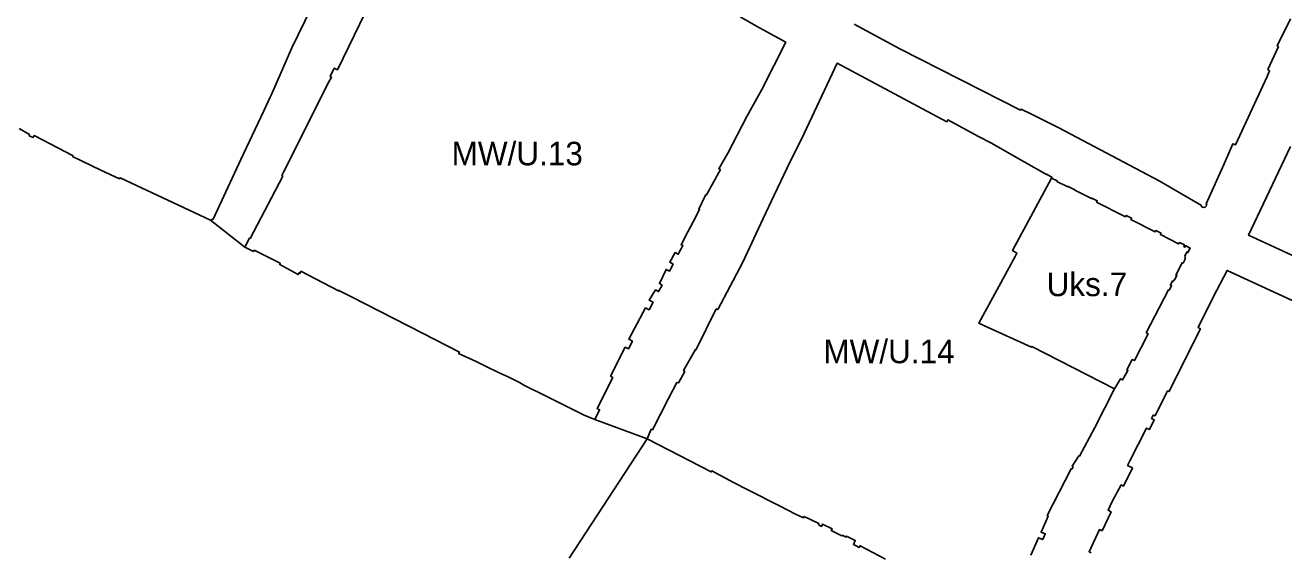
# Model space of a CAD drawing. Extents: x 7423367 to 7424726, y 5546744 to 5548391.
# Drawn here: x 7423927 to 7424194.2, y 5547840.8 to 5547952.8 of the extents above; entities that cross this region are included whole.
import ezdxf

# ---------------------------------------------------------------- set-up
doc = ezdxf.new("R2010")
doc.units = 0
doc.layers.add('linie_rozgraniczajace', color=7, linetype='Continuous')
doc.layers.add('oznaczenia_przeznaczen', color=7, linetype='Continuous')

msp = doc.modelspace()

# ---------------------------------------------------------------- linework, layer by layer
at = {"layer": 'linie_rozgraniczajace'}
for points in [[(7424002.7, 5547962.78), (7423993.29, 5547943.33), (7423992.63, 5547943.68), (7423991.75, 5547941.94), (7423992.02, 5547941.8), (7423991.4, 5547940.63), (7423990.46, 5547938.9), (7423983.05, 5547923.94), (7423981.87, 5547921.59), (7423981.51, 5547920.89), (7423981.69, 5547920.8), (7423974.77, 5547907.55), (7423974.64, 5547907.62), (7423973.68, 5547905.68), (7423966.33, 5547911.4), (7423966.92, 5547911.63), (7423972.83, 5547924.32), (7423977.68, 5547934.66), (7423979.01, 5547937.55), (7423979.3, 5547938.13), (7423983.64, 5547948.01), (7423987.74, 5547956.39)], [(7424078.76, 5547954.61), (7424082.89, 5547952.26), (7424088.46, 5547949.18), (7424083.38, 5547939.15), (7424080.22, 5547933.41), (7424076.17, 5547925.64), (7424074.24, 5547922.34), (7424074.58, 5547922.16), (7424071.66, 5547916.78), (7424071.52, 5547916.86), (7424069.97, 5547913.79), (7424070.15, 5547913.7), (7424068.8, 5547911.1), (7424067.69, 5547908.98), (7424066.23, 5547906.21), (7424066.61, 5547906.02), (7424065.64, 5547904.2), (7424064.97, 5547904.56), (7424063.83, 5547902.49), (7424064.55, 5547902.12), (7424063.76, 5547900.6), (7424063.06, 5547900.97), (7424061.64, 5547897.97), (7424062.24, 5547897.61), (7424061.46, 5547896.27), (7424060.83, 5547896.64), (7424059.49, 5547894.42), (7424060.28, 5547894.02), (7424059.46, 5547892.41), (7424058.69, 5547892.82), (7424055.18, 5547886.15), (7424055.91, 5547885.78), (7424055.09, 5547884.15), (7424054.4, 5547884.45), (7424051.22, 5547878.32), (7424051.78, 5547878.01), (7424048.41, 5547871.45), (7424048.94, 5547871.19), (7424047.91, 5547869.11), (7424045.7, 5547870.04), (7424037.48, 5547874.13), (7424033, 5547876.33), (7424031.91, 5547876.94), (7424029.7, 5547878.12), (7424027.6, 5547879.02), (7424027.21, 5547879.24), (7424025.15, 5547880.24), (7424024.28, 5547880.66), (7424022.72, 5547881.4), (7424021.94, 5547881.79), (7424019.78, 5547882.77), (7424019.03, 5547883.15), (7424019.18, 5547883.44), (7424011.38, 5547887.44), (7423996.29, 5547895.17), (7423993.59, 5547896.53), (7423993.52, 5547896.41), (7423985.54, 5547900.58), (7423985.34, 5547900.14), (7423985.11, 5547900.24), (7423984.95, 5547899.89), (7423981.05, 5547902), (7423981.18, 5547902.29), (7423975.63, 5547905.04), (7423975.48, 5547904.75), (7423973.68, 5547905.68), (7423974.64, 5547907.62), (7423974.77, 5547907.55), (7423981.69, 5547920.8), (7423981.51, 5547920.89), (7423981.87, 5547921.59), (7423983.05, 5547923.94), (7423990.46, 5547938.9), (7423991.4, 5547940.63), (7423992.02, 5547941.8), (7423991.75, 5547941.94), (7423992.63, 5547943.68), (7423993.29, 5547943.33), (7424002.7, 5547962.78)], [(7423987.74, 5547956.39), (7423983.64, 5547948.01), (7423979.3, 5547938.13), (7423979.01, 5547937.55), (7423977.68, 5547934.66), (7423972.83, 5547924.32), (7423966.92, 5547911.63), (7423966.33, 5547911.4), (7423957.28, 5547915.66), (7423947.17, 5547920.43), (7423947.03, 5547920.17), (7423943.08, 5547922.06), (7423937.1, 5547924.94), (7423937.19, 5547925.09), (7423928.92, 5547929.38), (7423928.72, 5547928.94), (7423927.85, 5547929.33), (7423927.97, 5547929.6), (7423925.73, 5547930.91)], [(7424140.46, 5547840.34), (7424142.09, 5547844.01), (7424143.01, 5547843.64), (7424143.53, 5547844.83), (7424142.63, 5547845.23), (7424144.13, 5547848.64), (7424143.94, 5547848.73), (7424148.99, 5547858.67), (7424149.16, 5547858.59), (7424149.44, 5547859.05), (7424149.26, 5547859.2), (7424150.62, 5547861.41), (7424150.79, 5547861.32), (7424153.96, 5547867.28), (7424158.25, 5547875.6), (7424159.47, 5547877.76), (7424159.95, 5547877.54), (7424161.07, 5547879.53), (7424160.85, 5547879.66), (7424161.97, 5547881.85), (7424162.46, 5547881.63), (7424165.35, 5547887.33), (7424164.95, 5547887.54), (7424169.67, 5547896.63), (7424169.83, 5547896.59), (7424170.32, 5547897.5), (7424170.08, 5547897.63), (7424170.53, 5547898.54), (7424170.68, 5547898.46), (7424170.89, 5547898.77), (7424170.98, 5547898.74), (7424171.46, 5547899.65), (7424171.25, 5547899.75), (7424172.58, 5547902.39), (7424172.78, 5547902.31), (7424173.27, 5547903.27), (7424173.13, 5547903.35), (7424173.28, 5547903.67), (7424173.12, 5547903.77), (7424173.56, 5547904.68), (7424173.8, 5547904.54), (7424174.28, 5547905.49), (7424173.33, 5547905.99), (7424173.18, 5547905.71), (7424172.91, 5547905.87), (7424173.05, 5547906.16), (7424172.03, 5547906.68), (7424171.83, 5547906.38), (7424167.96, 5547908.35), (7424168.11, 5547908.64), (7424167, 5547909.21), (7424166.84, 5547908.93), (7424161.68, 5547911.57), (7424161.84, 5547911.86), (7424160.71, 5547912.42), (7424160.55, 5547912.12), (7424154.4, 5547915.26), (7424154.56, 5547915.55), (7424153.43, 5547916.11), (7424153.37, 5547916), (7424149.77, 5547917.79), (7424149.8, 5547917.83), (7424148.38, 5547918.59), (7424148.31, 5547918.49), (7424146, 5547919.65), (7424146.06, 5547919.76), (7424144.84, 5547920.37), (7424144.94, 5547920.57), (7424143.81, 5547921.19), (7424143.77, 5547921.11), (7424139.04, 5547923.78), (7424131.97, 5547927.83), (7424129.35, 5547929.17), (7424122.83, 5547932.69), (7424122.64, 5547932.33), (7424099.38, 5547944.77), (7424091.79, 5547928.64), (7424089.43, 5547924.01), (7424086.02, 5547916.7), (7424083.68, 5547911.78), (7424079.28, 5547902.37), (7424074.01, 5547892.44), (7424073.69, 5547892.6), (7424069.44, 5547883.97), (7424069.32, 5547883.99), (7424066.78, 5547879.5), (7424067.02, 5547879.3), (7424065.7, 5547876.9), (7424065.35, 5547876.99), (7424063.59, 5547873.55), (7424060.14, 5547866.91), (7424059.9, 5547867.04), (7424059.01, 5547865.01), (7424047.91, 5547869.11), (7424048.94, 5547871.19), (7424048.41, 5547871.45), (7424051.78, 5547878.01), (7424051.22, 5547878.32), (7424054.4, 5547884.45), (7424055.09, 5547884.15), (7424055.91, 5547885.78), (7424055.18, 5547886.15), (7424058.69, 5547892.82), (7424059.46, 5547892.41), (7424060.28, 5547894.02), (7424059.49, 5547894.42), (7424060.83, 5547896.64), (7424061.46, 5547896.27), (7424062.24, 5547897.61), (7424061.64, 5547897.97), (7424063.06, 5547900.97), (7424063.76, 5547900.6), (7424064.55, 5547902.12), (7424063.83, 5547902.49), (7424064.97, 5547904.56), (7424065.64, 5547904.2), (7424066.61, 5547906.02), (7424066.23, 5547906.21), (7424067.69, 5547908.98), (7424068.8, 5547911.1), (7424070.15, 5547913.7), (7424069.97, 5547913.79), (7424071.52, 5547916.86), (7424071.66, 5547916.78), (7424074.58, 5547922.16), (7424074.24, 5547922.34), (7424076.17, 5547925.64), (7424080.22, 5547933.41), (7424083.38, 5547939.15), (7424088.46, 5547949.18), (7424082.89, 5547952.26), (7424078.76, 5547954.61)], [(7424195.6, 5547954.18), (7424192.76, 5547948.4), (7424193.02, 5547948.27), (7424190.77, 5547943.38), (7424191.12, 5547943.15), (7424190.93, 5547942.65), (7424190.6, 5547941.92), (7424183.9, 5547927.38), (7424183.31, 5547927.65), (7424181.5, 5547923.36), (7424177.68, 5547914.91), (7424177.8, 5547914.86), (7424177.75, 5547914.65), (7424177.65, 5547914.42), (7424177.48, 5547914.21), (7424177.28, 5547914.14), (7424176.87, 5547914.22), (7424176.61, 5547914.4), (7424176.67, 5547914.51), (7424167.7, 5547919.74), (7424146.39, 5547930.99), (7424140.63, 5547933.93), (7424138.41, 5547934.95), (7424138.27, 5547934.77), (7424112.68, 5547947.82), (7424102.94, 5547953.02)], [(7424102.94, 5547953.02), (7424112.68, 5547947.82), (7424138.27, 5547934.77), (7424138.41, 5547934.95), (7424140.63, 5547933.93), (7424146.39, 5547930.99), (7424167.7, 5547919.74), (7424176.67, 5547914.51), (7424176.61, 5547914.4), (7424176.87, 5547914.22), (7424177.28, 5547914.14), (7424177.48, 5547914.21), (7424177.65, 5547914.42), (7424177.75, 5547914.65), (7424177.8, 5547914.86), (7424177.68, 5547914.91), (7424181.5, 5547923.36), (7424183.31, 5547927.65), (7424183.9, 5547927.38), (7424190.6, 5547941.92), (7424190.93, 5547942.65), (7424191.12, 5547943.15), (7424190.77, 5547943.38), (7424193.02, 5547948.27), (7424192.76, 5547948.4), (7424195.6, 5547954.18)], [(7424109.63, 5547839.47), (7424104.24, 5547842.31), (7424104.06, 5547841.99), (7424103.38, 5547842.33), (7424102.82, 5547842.62), (7424103.21, 5547843.41), (7424101.33, 5547844.34), (7424101.26, 5547844.18), (7424100.44, 5547844.57), (7424100.37, 5547844.41), (7424098.11, 5547845.54), (7424098.27, 5547845.93), (7424096.27, 5547846.92), (7424096.02, 5547846.42), (7424095.38, 5547846.78), (7424095.47, 5547847.08), (7424092.37, 5547848.57), (7424092.19, 5547848.23), (7424091.18, 5547848.73), (7424090.51, 5547849.05), (7424087.24, 5547850.7), (7424080.55, 5547854.1), (7424077.39, 5547855.73), (7424072.74, 5547858.22), (7424072.62, 5547858.01), (7424059.01, 5547865.01), (7424059.9, 5547867.04), (7424060.14, 5547866.91), (7424063.59, 5547873.55), (7424065.35, 5547876.99), (7424065.7, 5547876.9), (7424067.02, 5547879.3), (7424066.78, 5547879.5), (7424069.32, 5547883.99), (7424069.44, 5547883.97), (7424073.69, 5547892.6), (7424074.01, 5547892.44), (7424079.28, 5547902.37), (7424083.68, 5547911.78), (7424086.02, 5547916.7), (7424089.43, 5547924.01), (7424091.79, 5547928.64), (7424099.38, 5547944.77), (7424122.64, 5547932.33), (7424122.83, 5547932.69), (7424129.35, 5547929.17), (7424131.97, 5547927.83), (7424139.04, 5547923.78), (7424143.77, 5547921.11), (7424143.81, 5547921.19), (7424144.94, 5547920.57), (7424144.84, 5547920.37), (7424136.6, 5547904.96), (7424137.5, 5547904.43), (7424137.19, 5547903.87), (7424133.69, 5547897.38), (7424129.45, 5547889.54), (7424130.66, 5547889.01), (7424140.6, 5547884.44), (7424140.7, 5547884.64), (7424158.25, 5547875.6), (7424153.96, 5547867.28), (7424150.79, 5547861.32), (7424150.62, 5547861.41), (7424149.26, 5547859.2), (7424149.44, 5547859.05), (7424149.16, 5547858.59), (7424148.99, 5547858.67), (7424143.94, 5547848.73), (7424144.13, 5547848.64), (7424142.63, 5547845.23), (7424143.53, 5547844.83), (7424143.01, 5547843.64), (7424142.09, 5547844.01), (7424140.46, 5547840.34)], [(7423925.73, 5547930.91), (7423927.97, 5547929.6), (7423927.85, 5547929.33), (7423928.72, 5547928.94), (7423928.92, 5547929.38), (7423937.19, 5547925.09), (7423937.1, 5547924.94), (7423943.08, 5547922.06), (7423947.03, 5547920.17), (7423947.17, 5547920.43), (7423957.28, 5547915.66), (7423966.33, 5547911.4), (7423973.68, 5547905.68), (7423975.48, 5547904.75), (7423975.63, 5547905.04), (7423981.18, 5547902.29), (7423981.05, 5547902), (7423984.95, 5547899.89), (7423985.11, 5547900.24), (7423985.34, 5547900.14), (7423985.54, 5547900.58), (7423993.52, 5547896.41), (7423993.59, 5547896.53), (7423996.29, 5547895.17), (7424011.38, 5547887.44), (7424019.18, 5547883.44), (7424019.03, 5547883.15), (7424019.78, 5547882.77), (7424021.94, 5547881.79), (7424022.72, 5547881.4), (7424024.28, 5547880.66), (7424025.15, 5547880.24), (7424027.21, 5547879.24), (7424027.6, 5547879.02), (7424029.7, 5547878.12), (7424031.91, 5547876.94), (7424033, 5547876.33), (7424037.48, 5547874.13), (7424045.7, 5547870.04), (7424047.91, 5547869.11), (7424059.01, 5547865.01), (7424042.47, 5547839.7)], [(7424210.59, 5547897.18), (7424186.66, 5547908.22), (7424195.58, 5547927.09)], [(7424195.58, 5547927.09), (7424186.66, 5547908.22), (7424210.59, 5547897.18)], [(7424153.29, 5547840.8), (7424152.81, 5547841.05), (7424155.01, 5547845.77), (7424155.6, 5547845.51), (7424157.48, 5547849.52), (7424156.85, 5547849.86), (7424157.71, 5547851.71), (7424159.64, 5547855.23), (7424160.12, 5547854.97), (7424162.01, 5547858.83), (7424160.99, 5547859.36), (7424161.48, 5547860.35), (7424165.04, 5547867.29), (7424165.62, 5547866.99), (7424166.65, 5547869.03), (7424166.07, 5547869.34), (7424166.44, 5547870.07), (7424166.83, 5547869.9), (7424169.27, 5547874.78), (7424169.48, 5547875.2), (7424169.79, 5547875.04), (7424175.14, 5547885.75), (7424176.45, 5547888.35), (7424175.95, 5547888.67), (7424176.73, 5547890.29), (7424179.95, 5547896.59), (7424182.16, 5547900.77), (7424203.9, 5547890.69)], [(7424203.9, 5547890.69), (7424182.16, 5547900.77), (7424179.95, 5547896.59), (7424176.73, 5547890.29), (7424175.95, 5547888.67), (7424176.45, 5547888.35), (7424175.14, 5547885.75), (7424169.79, 5547875.04), (7424169.48, 5547875.2), (7424169.27, 5547874.78), (7424166.83, 5547869.9), (7424166.44, 5547870.07), (7424166.07, 5547869.34), (7424166.65, 5547869.03), (7424165.62, 5547866.99), (7424165.04, 5547867.29), (7424161.48, 5547860.35), (7424160.99, 5547859.36), (7424162.01, 5547858.83), (7424160.12, 5547854.97), (7424159.64, 5547855.23), (7424157.71, 5547851.71), (7424156.85, 5547849.86), (7424157.48, 5547849.52), (7424155.6, 5547845.51), (7424155.01, 5547845.77), (7424152.81, 5547841.05), (7424153.29, 5547840.8)], [(7424042.47, 5547839.7), (7424059.01, 5547865.01), (7424072.62, 5547858.01), (7424072.74, 5547858.22), (7424077.39, 5547855.73), (7424080.55, 5547854.1), (7424087.24, 5547850.7), (7424090.51, 5547849.05), (7424091.18, 5547848.73), (7424092.19, 5547848.23), (7424092.37, 5547848.57), (7424095.47, 5547847.08), (7424095.38, 5547846.78), (7424096.02, 5547846.42), (7424096.27, 5547846.92), (7424098.27, 5547845.93), (7424098.11, 5547845.54), (7424100.37, 5547844.41), (7424100.44, 5547844.57), (7424101.26, 5547844.18), (7424101.33, 5547844.34), (7424103.21, 5547843.41), (7424102.82, 5547842.62), (7424103.38, 5547842.33), (7424104.06, 5547841.99), (7424104.24, 5547842.31), (7424109.63, 5547839.47)]]:
    msp.add_lwpolyline(points, dxfattribs=at)
msp.add_lwpolyline([(7424129.45, 5547889.54), (7424133.69, 5547897.38), (7424137.19, 5547903.87), (7424137.5, 5547904.43), (7424136.6, 5547904.96), (7424144.84, 5547920.37), (7424146.06, 5547919.76), (7424146, 5547919.65), (7424148.31, 5547918.49), (7424148.38, 5547918.59), (7424149.8, 5547917.83), (7424149.77, 5547917.79), (7424153.37, 5547916), (7424153.43, 5547916.11), (7424154.56, 5547915.55), (7424154.4, 5547915.26), (7424160.55, 5547912.12), (7424160.71, 5547912.42), (7424161.84, 5547911.86), (7424161.68, 5547911.57), (7424166.84, 5547908.93), (7424167, 5547909.21), (7424168.11, 5547908.64), (7424167.96, 5547908.35), (7424171.83, 5547906.38), (7424172.03, 5547906.68), (7424173.05, 5547906.16), (7424172.91, 5547905.87), (7424173.18, 5547905.71), (7424173.33, 5547905.99), (7424174.28, 5547905.49), (7424173.8, 5547904.54), (7424173.56, 5547904.68), (7424173.12, 5547903.77), (7424173.28, 5547903.67), (7424173.13, 5547903.35), (7424173.27, 5547903.27), (7424172.78, 5547902.31), (7424172.58, 5547902.39), (7424171.25, 5547899.75), (7424171.46, 5547899.65), (7424170.98, 5547898.74), (7424170.89, 5547898.77), (7424170.68, 5547898.46), (7424170.53, 5547898.54), (7424170.08, 5547897.63), (7424170.32, 5547897.5), (7424169.83, 5547896.59), (7424169.67, 5547896.63), (7424164.95, 5547887.54), (7424165.35, 5547887.33), (7424162.46, 5547881.63), (7424161.97, 5547881.85), (7424160.85, 5547879.66), (7424161.07, 5547879.53), (7424159.95, 5547877.54), (7424159.47, 5547877.76), (7424158.25, 5547875.6), (7424140.7, 5547884.64), (7424140.6, 5547884.44), (7424130.66, 5547889.01)], close=True, dxfattribs=at)

# ---------------------------------------------------------------- texts
at = {"layer": 'oznaczenia_przeznaczen'}
for s, p in [('MW/U.13', (7424017.53, 5547923.06)), ('Uks.7', (7424143.81, 5547895.3)), ('MW/U.14', (7424096.43, 5547881.07))]:
    msp.add_text(s, height=5, dxfattribs=at).set_placement(p)

doc.saveas('drawing.dxf')
